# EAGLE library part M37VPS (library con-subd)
SUB-D
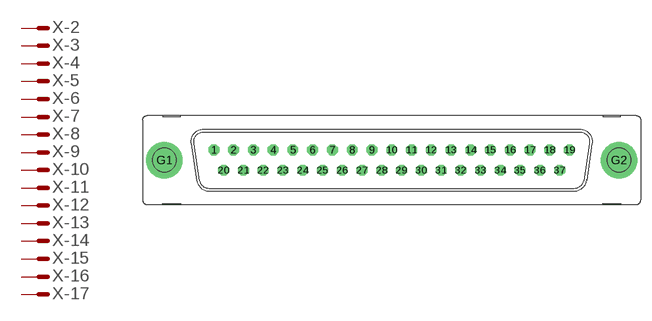
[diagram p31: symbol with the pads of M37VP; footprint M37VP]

Designator prefix X; gates -2=M -3=M -4=M -5=M -6=M -7=M -8=M -9=M -10=M -11=M -12=M -13=M -14=M -15=M -16=M -17=M -18=M -19=M -20=M -21=M -22=M -23=M -24=M -25=M -26=M -27=M -28=M -29=M -30=M -31=M -32=M -33=M -34=M -35=M -36=M -37=M -G=GND -1=MV

## M37VPS (OC_FARNELL: unknown; OC_NEWARK: unknown)  [M37VP]
1  -1:M  pas
2  -2:M  pas
3  -3:M  pas
4  -4:M  pas
5  -5:M  pas
6  -6:M  pas
7  -7:M  pas
8  -8:M  pas
9  -9:M  pas
10  -10:M  pas
11  -11:M  pas
12  -12:M  pas
13  -13:M  pas
14  -14:M  pas
15  -15:M  pas
16  -16:M  pas
17  -17:M  pas
18  -18:M  pas
19  -19:M  pas
20  -20:M  pas
21  -21:M  pas
22  -22:M  pas
23  -23:M  pas
24  -24:M  pas
25  -25:M  pas
26  -26:M  pas
27  -27:M  pas
28  -28:M  pas
29  -29:M  pas
30  -30:M  pas
31  -31:M  pas
32  -32:M  pas
33  -33:M  pas
34  -34:M  pas
35  -35:M  pas
36  -36:M  pas
37  -37:M  pas
G1  -G:G1  pas
G2  -G:G2  pas

## Footprint M37VP (pad centres in mm)
SUB-D
drill 1.016 octagon: 1 -24.841,1.422; 2 -22.098,1.422; 3 -19.329,1.422; 4 -16.561,1.422; 5 -13.818,1.422; 6 -11.049,1.422; 7 -8.28,1.422; 8 -5.512,1.422; 9 -2.769,1.422; 10 0,1.422; 11 2.769,1.422; 12 5.512,1.422; 13 8.28,1.422; 14 11.049,1.422; 15 13.792,1.422; 16 16.561,1.422; 17 19.329,1.422; 18 22.073,1.422; 19 24.841,1.422; 20 -23.47,-1.422; 21 -20.701,-1.422; 22 -17.958,-1.422; 23 -15.189,-1.422; 24 -12.421,-1.422; 25 -9.652,-1.422; 26 -6.909,-1.422; 27 -4.14,-1.422; 28 -1.372,-1.422; 29 1.372,-1.422; 30 4.14,-1.422; 31 6.909,-1.422; 32 9.652,-1.422; 33 12.421,-1.422; 34 15.189,-1.422; 35 17.932,-1.422; 36 20.701,-1.422; 37 23.47,-1.422
drill 3.302 pad 5.08 round: G1 -31.75,0; G2 31.75,0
